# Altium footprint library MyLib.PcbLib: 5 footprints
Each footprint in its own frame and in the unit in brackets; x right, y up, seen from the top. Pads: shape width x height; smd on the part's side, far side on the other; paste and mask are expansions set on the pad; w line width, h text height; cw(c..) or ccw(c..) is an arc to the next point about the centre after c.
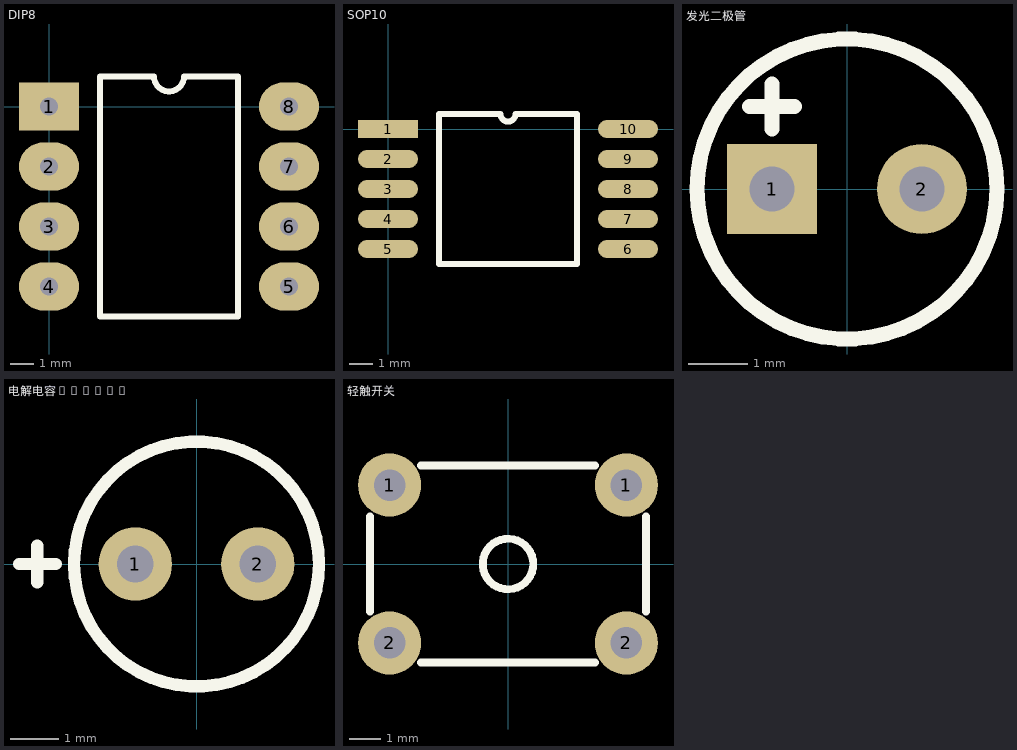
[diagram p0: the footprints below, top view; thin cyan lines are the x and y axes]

## DIP8 [mil]
pads (8):
  rect 100x80 hole 30: 1(0,0)
  oval 100x80 hole 30: 2(0,-100) 3(0,-200) 4(0,-300) 5(400,-300) 6(400,-200) 7(400,-100) 8(400,0)
Top Overlay:
  lines w10: 85,-350 315,-350 315,50 225,50 cw(c200,50) 175,50 85,50 85,-350

## SOP10 [mil]
pads (10):
  rect 100x30 smd: 1(0,0)
  oval 100x30 smd: 2(0,-50) 3(0,-100) 4(0,-150) 5(0,-200) 6(400,-200) 7(400,-150) 8(400,-100) 9(400,-50) 10(400,0)
Top Overlay:
  lines w10: 85,-225 315,-225 315,25 212.5,25 cw(c200,25) 187.5,25 85,25 85,-225

## 发光二极管 [mil]
pads (2):
  rect 60x60 hole 30: 1(-50,0)
  round 60 hole 30: 2(50,0)
Top Overlay:
  circle w10: c0,0 r100
  lines w10: -65,55 -35,55 ; -50,40 -50,70

## 电解电容-100uF [mil]
pads (2):
  round 60 hole 30: 1(-50,0) 2(50,0)
Top Overlay:
  circle w10: c0,0 r100
  lines w10: -145,0 -115,0 ; -130,-15 -130,15

## 轻触开关 [mil]
pads (4):
  round 80 hole 40: 1(-150,100) 1(150,100) 2(-150,-100) 2(150,-100)
Top Overlay:
  circle w10: c0,0 r32.02
  lines w10: -175,-60 -175,60 ; -110,-125 110,-125 ; -110,125 110,125 ; 175,-60 175,60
